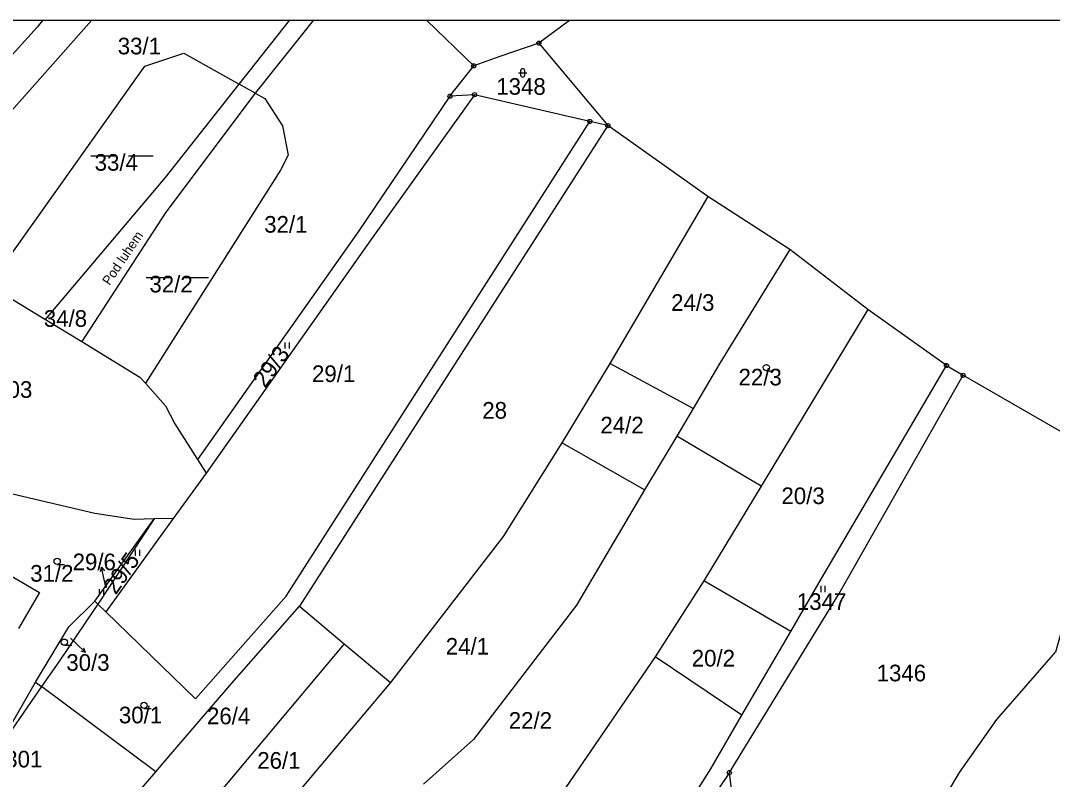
# Model space of a CAD drawing. Extents: x -564516 to -563466, y -1163913 to -1163170.
# Drawn here: x -564146.8 to -563898.7, y -1163352.4 to -1163170 of the extents above; entities that cross this region are included whole.
import ezdxf

# ---------------------------------------------------------------- set-up
doc = ezdxf.new("R2010")
doc.units = 0
for name, color, linetype in [('_parcely přehledka', 7, 'Continuous'), ('Hranice parcel', 7, 'Continuous'), ('Parcelní čísla', 7, 'Continuous'), ('Pop  PČ popisy', 7, 'Continuous'), ('Značky bodu BP', 7, 'Continuous'), ('Značky kultur', 7, 'Continuous')]:
    doc.layers.add(name, color=color, linetype=linetype)

msp = doc.modelspace()

# ---------------------------------------------------------------- linework, layer by layer
at = {"layer": '_parcely přehledka'}
msp.add_line((-563466.35, -1163170.03), (-564516.35, -1163170.03), dxfattribs=at)
at = {"layer": 'Hranice parcel'}
for p, q in [((-564094.24, -1163185.33), (-564082.11, -1163170.03)), ((-564076.47, -1163170.03), (-564090.37, -1163187.5)), ((-564037.83, -1163180.91), (-564049.13, -1163170.03)), ((-564014.78, -1163170.03), (-564022.17, -1163175.45)), ((-564022.17, -1163175.45), (-564005.56, -1163195.27)), ((-564107.57, -1163177.86), (-564094.24, -1163185.33)), ((-564043.55, -1163188.2), (-564037.83, -1163180.91)), ((-564090.37, -1163187.5), (-564094.24, -1163185.33)), ((-564090.37, -1163187.5), (-564088.09, -1163188.77)), ((-564037.64, -1163187.84), (-564043.55, -1163188.2)), ((-564009.92, -1163194.27), (-564037.64, -1163187.84)), ((-564005.56, -1163195.27), (-564009.92, -1163194.27)), ((-564005.56, -1163195.27), (-564079.76, -1163310.83)), ((-563981.49, -1163212.35), (-564005.56, -1163195.27)), ((-563981.49, -1163212.35), (-564005.06, -1163252.44)), ((-563961.84, -1163225.03), (-563981.49, -1163212.35)), ((-563943.05, -1163239.52), (-563961.84, -1163225.03)), ((-564150.43, -1163236.01), (-564140.81, -1163241.88)), ((-563943.05, -1163239.52), (-563968.7, -1163281.94)), ((-563924.13, -1163252.95), (-563943.05, -1163239.52)), ((-564140.81, -1163241.88), (-564132.1, -1163247.19)), ((-564132.1, -1163247.19), (-564118.13, -1163255.72)), ((-564005.06, -1163252.44), (-564016.61, -1163271.58)), ((-563985.08, -1163263.28), (-564005.06, -1163252.44)), ((-563924.13, -1163252.95), (-563920.13, -1163255.3)), ((-564118.13, -1163255.72), (-564116.8, -1163257.21)), ((-563985.08, -1163263.28), (-563989, -1163269.91)), ((-564109.73, -1163266.95), (-564104.24, -1163275.55)), ((-563996.73, -1163282.82), (-564016.61, -1163271.58)), ((-563989, -1163269.91), (-563996.73, -1163282.82)), ((-563968.7, -1163281.94), (-563989, -1163269.91)), ((-564104.24, -1163275.55), (-564102.16, -1163278.8)), ((-564102.16, -1163278.8), (-564110.16, -1163289.7)), ((-563968.7, -1163281.94), (-563982.5, -1163304.75)), ((-564128.96, -1163309.61), (-564114.72, -1163289.83)), ((-564114.72, -1163289.83), (-564128.23, -1163310.32)), ((-564110.16, -1163289.7), (-564126.35, -1163312.15)), ((-564114.72, -1163289.83), (-564119.51, -1163289.97)), ((-564110.16, -1163289.7), (-564114.72, -1163289.83)), ((-563982.5, -1163304.75), (-563994.23, -1163322.96)), ((-563961.53, -1163316.94), (-563982.5, -1163304.75)), ((-564128.23, -1163310.32), (-564129.25, -1163311.86)), ((-564128.96, -1163309.61), (-564128.23, -1163310.32)), ((-564126.35, -1163312.15), (-564128.23, -1163310.32)), ((-564079.76, -1163310.83), (-564068.99, -1163319.83)), ((-564129.25, -1163311.86), (-564137.65, -1163324.23)), ((-563973.36, -1163336.98), (-563961.53, -1163316.94)), ((-564068.99, -1163319.83), (-564110.43, -1163369.2)), ((-564068.99, -1163319.83), (-564057.87, -1163329.13)), ((-563973.36, -1163336.98), (-563994.23, -1163322.96)), ((-564137.65, -1163324.23), (-564141.76, -1163330.16)), ((-564143.24, -1163329.06), (-564141.76, -1163330.16)), ((-564141.76, -1163330.16), (-564161.84, -1163359.11)), ((-564114.33, -1163350.65), (-564141.76, -1163330.16)), ((-564057.87, -1163329.13), (-564084.64, -1163360.96)), ((-564122.2, -1163359.75), (-564114.33, -1163350.65))]:
    msp.add_line(p, q, dxfattribs=at)
for points in [[(-564141.58, -1163170.03), (-564142.86, -1163171.64), (-564177.26, -1163209.56), (-564183.19, -1163216.68), (-564187.1, -1163222.59), (-564190.65, -1163229.22), (-564197.64, -1163242.84)], [(-564129.74, -1163170.03), (-564177.65, -1163223.93)], [(-564022.17, -1163175.45), (-564031.54, -1163178.67), (-564037.83, -1163180.91)], [(-564153.08, -1163231.82), (-564116.96, -1163180.97), (-564107.57, -1163177.86)], [(-564140.81, -1163241.88), (-564112.01, -1163207.73), (-564094.24, -1163185.33)], [(-564090.37, -1163187.5), (-564111.93, -1163216.11), (-564132.1, -1163247.19)], [(-564088.09, -1163188.77), (-564083.82, -1163195.29), (-564082.5, -1163202.4), (-564084.33, -1163205.99), (-564116.8, -1163257.21)], [(-564043.55, -1163188.2), (-564065.63, -1163220.8), (-564104.24, -1163275.55)], [(-564037.64, -1163187.84), (-564062.61, -1163222.76), (-564102.16, -1163278.8)], [(-564126.35, -1163312.15), (-564104.79, -1163333.11), (-564082.96, -1163308.41), (-564009.92, -1163194.27)], [(-563961.84, -1163225.03), (-563978.61, -1163252.35), (-563985.08, -1163263.28)], [(-563961.53, -1163316.94), (-563954.75, -1163305.16), (-563924.13, -1163252.95)], [(-563976.35, -1163350.81), (-563949.95, -1163307.8), (-563920.13, -1163255.3)], [(-563920.13, -1163255.3), (-563884.9, -1163275.51), (-563897.93, -1163321.91)], [(-564116.8, -1163257.21), (-564111.98, -1163262.64), (-564109.73, -1163266.95)], [(-564016.61, -1163271.58), (-564030.78, -1163294.08), (-564057.87, -1163329.13)], [(-564119.51, -1163289.97), (-564128.93, -1163288.56), (-564148.76, -1163283.85)], [(-563996.73, -1163282.82), (-564013.09, -1163310.6), (-564037.85, -1163342.83), (-564049.89, -1163353.59)], [(-564154.68, -1163300.34), (-564142.31, -1163307.51), (-564147.35, -1163316.17)], [(-564143.24, -1163329.06), (-564135.26, -1163315.77), (-564128.96, -1163309.61)], [(-564114.33, -1163350.65), (-564110.68, -1163346.43), (-564095.99, -1163329.29), (-564079.76, -1163310.83)], [(-563994.23, -1163322.96), (-564015.76, -1163354.51), (-564031.92, -1163370.39)], [(-563946.81, -1163394.51), (-563921.02, -1163350.78), (-563912.02, -1163338.09), (-563897.93, -1163321.91)], [(-564152.26, -1163344.36), (-564149.64, -1163340.3), (-564143.24, -1163329.06)], [(-563989.46, -1163363.63), (-563980.83, -1163349.88), (-563973.36, -1163336.98)], [(-563976.35, -1163350.81), (-563986.4, -1163365.77), (-563989.46, -1163363.63)], [(-563972.82, -1163378.35), (-563973.64, -1163372.74), (-563976.35, -1163350.81)]]:
    msp.add_lwpolyline(points, dxfattribs=at)
at = {"layer": 'Pop  PČ popisy'}
for p, q in [((-564127.39, -1163301.46), (-564127.65, -1163302.54)), ((-564126.71, -1163304.38), (-564127.39, -1163301.46)), ((-564127.39, -1163301.46), (-564126.67, -1163302.32)), ((-564126.22, -1163306.41), (-564126.71, -1163304.38)), ((-564134.86, -1163318.5), (-564133.39, -1163319.87)), ((-564133.39, -1163319.87), (-564131.2, -1163321.92)), ((-564131.2, -1163321.92), (-564132.27, -1163321.6)), ((-564131.2, -1163321.92), (-564131.59, -1163320.87))]:
    msp.add_line(p, q, dxfattribs=at)
at = {"layer": 'Značky bodu BP'}
for centre, radius in [((-564022.17, -1163175.45), 0.5), ((-564022.17, -1163175.45), 0.0303), ((-564037.83, -1163180.91), 0.5), ((-564037.83, -1163180.91), 0.0303), ((-564037.64, -1163187.84), 0.5), ((-564043.55, -1163188.2), 0.5), ((-564043.55, -1163188.2), 0.0303), ((-564037.64, -1163187.84), 0.0303), ((-564009.92, -1163194.27), 0.5), ((-564009.92, -1163194.27), 0.0303), ((-564005.56, -1163195.27), 0.5), ((-564005.56, -1163195.27), 0.0303), ((-563924.13, -1163252.95), 0.5), ((-563924.13, -1163252.95), 0.0303), ((-563920.13, -1163255.3), 0.5), ((-563920.13, -1163255.3), 0.0303), ((-563976.35, -1163350.81), 0.5), ((-563976.35, -1163350.81), 0.0303)]:
    msp.add_circle(centre, radius, dxfattribs=at)
at = {"layer": 'Značky kultur'}
for p, q in [((-564027.06, -1163182.59), (-564025.06, -1163182.59)), ((-564026.56, -1163182.09), (-564026.56, -1163183.09)), ((-564025.56, -1163183.09), (-564025.56, -1163182.09)), ((-564129.9, -1163202.57), (-564123.9, -1163202.57)), ((-564120.9, -1163202.57), (-564114.9, -1163202.57)), ((-564116.65, -1163231.83), (-564110.65, -1163231.83)), ((-564107.65, -1163231.83), (-564101.65, -1163231.83)), ((-564083.18, -1163248.89), (-564083.18, -1163247.39)), ((-564082.18, -1163248.89), (-564082.18, -1163247.39)), ((-563967.45, -1163254.19), (-563965.7, -1163254.19)), ((-564119.15, -1163298.73), (-564119.15, -1163297.23)), ((-564118.15, -1163298.73), (-564118.15, -1163297.23)), ((-564138.02, -1163300.81), (-564136.27, -1163300.81)), ((-564127.84, -1163308.24), (-564127.84, -1163306.74)), ((-564126.84, -1163308.24), (-564126.84, -1163306.74)), ((-563954.3, -1163307.43), (-563954.3, -1163305.93)), ((-563953.3, -1163307.43), (-563953.3, -1163305.93)), ((-564136.29, -1163320.21), (-564134.54, -1163320.21)), ((-564117.13, -1163335.43), (-564115.38, -1163335.43))]:
    msp.add_line(p, q, dxfattribs=at)
for centre in [(-563967.45, -1163253.44), (-564138.02, -1163300.06), (-564136.29, -1163319.46), (-564117.13, -1163334.68)]:
    msp.add_circle(centre, 0.75, dxfattribs=at)
for centre, start, end in [((-564026.06, -1163182.09), 0, 180), ((-564026.06, -1163183.09), 180, 359.9879)]:
    msp.add_arc(centre, 0.5, start, end, dxfattribs=at)

# ---------------------------------------------------------------- texts
at = {"layer": 'Parcelní čísla'}
for s, p in [('33/1', (-564123.46, -1163178.14)), ('1348', (-564032.41, -1163187.86)), ('33/4', (-564129.01, -1163206.12)), ('32/1', (-564088.23, -1163221.01)), ('32/2', (-564115.84, -1163235.38)), ('24/3', (-563990.35, -1163239.81)), ('34/8', (-564141.24, -1163243.65)), ('29/1', (-564076.73, -1163256.92)), ('22/3', (-563974.14, -1163257.74)), ('103', (-564152.93, -1163260.72)), ('28', (-564035.78, -1163265.73)), ('24/2', (-564007.37, -1163269.28)), ('20/3', (-563963.82, -1163286.27)), ('29/6', (-564134.31, -1163302.17)), ('31/2', (-564144.51, -1163304.92)), ('1347', (-563960.11, -1163311.7)), ('24/1', (-564044.56, -1163322.46)), ('20/2', (-563985.4, -1163325.32)), ('30/3', (-564135.83, -1163326.35)), ('1346', (-563940.92, -1163328.88)), ('30/1', (-564123.18, -1163338.98)), ('26/4', (-564101.99, -1163339.21)), ('22/2', (-564029.41, -1163340.28)), ('1301', (-564153.49, -1163349.58)), ('26/1', (-564089.9, -1163349.89))]:
    msp.add_text(s, height=4, dxfattribs=at).set_placement(p)
for s, rotation, p in [('29/3', 54, (-564088.04, -1163258.56)), ('29/5', 55, (-564123.95, -1163308.28))]:
    msp.add_text(s, height=4, rotation=rotation, dxfattribs=at).set_placement(p)
at = {"layer": 'Pop  PČ popisy'}
msp.add_text('Pod luhem', height=2.3, rotation=56, dxfattribs=at).set_placement((-564125.44, -1163233.83))

doc.saveas('drawing.dxf')
